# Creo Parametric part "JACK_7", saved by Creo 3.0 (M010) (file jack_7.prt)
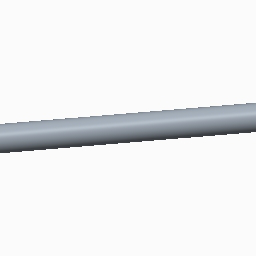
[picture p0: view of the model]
Units: millimeter Newton Second (mmNs); MM, TONNE, SECS

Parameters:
  PLACEMENT = "EXTERNAL"

Other parameters: MINOR_DIAMETER, PITCH

Created from: MMNS_PART_SOLID.PRT

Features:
  1. datum plane "RIGHT"
  2. datum plane "TOP"
  3. datum plane "FRONT"
  4. coordinate system
  5. protrusion
  6. chamfer

Surfaces: 6 plane, 4 cone, 2 cylinder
